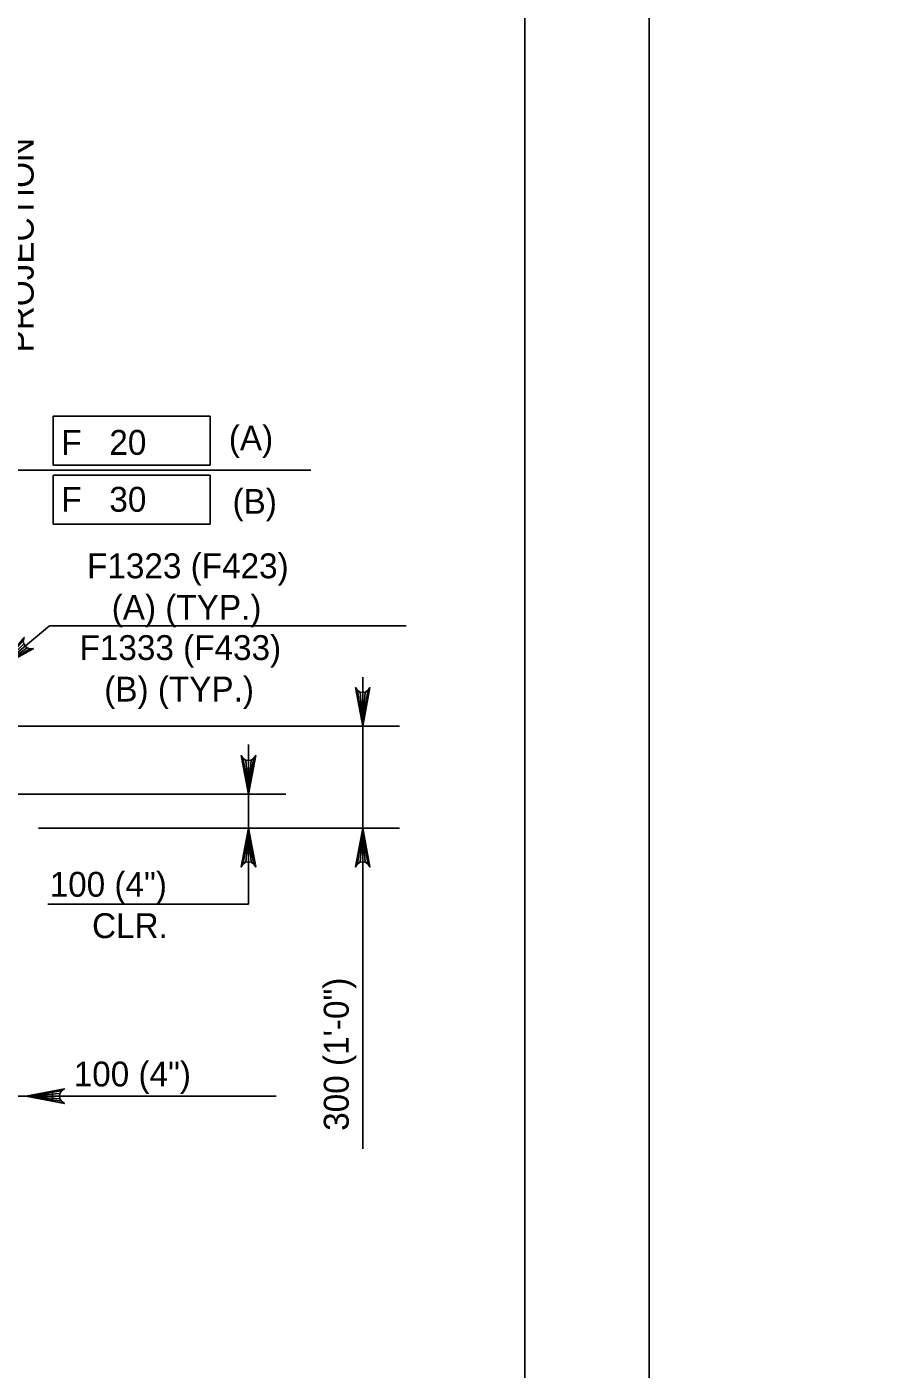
# Model space of a CAD drawing. Extents: x 638340 to 640241, y 295465 to 298435.
# Drawn here: x 639201.4 to 639303.6, y 296333.9 to 296495.7 of the extents above; entities that cross this region are included whole.
import ezdxf

# ---------------------------------------------------------------- set-up
doc = ezdxf.new("R2010")
doc.units = 0
for name, color, linetype in [('2', 7, 'Continuous'), ('3', 7, 'Continuous'), ('4', 7, 'Continuous'), ('PLT-BNDY', 7, 'Continuous')]:
    doc.layers.add(name, color=color, linetype=linetype)

msp = doc.modelspace()

# ---------------------------------------------------------------- linework, layer by layer
at = {"layer": '2'}
msp.add_line((639261.46, 296638.46), (639261.46, 296074.46), dxfattribs=at)
at = {"layer": '3'}
for p, q in [((639241.91, 296414.33), (639241.91, 296417.29)), ((639190.27, 296411.38), (639246.34, 296411.38)), ((639241.91, 296411.38), (639241.91, 296399.08)), ((639228.13, 296406.18), (639228.13, 296409.18)), ((639199.63, 296403.18), (639232.63, 296403.18)), ((639228.13, 296403.18), (639228.13, 296399.08)), ((639202.82, 296399.08), (639246.34, 296399.08)), ((639202.85, 296399.08), (639232.63, 296399.08)), ((639228.13, 296396.08), (639228.13, 296389.91)), ((639241.91, 296396.13), (639241.91, 296360.41)), ((639228.13, 296389.91), (639203.96, 296389.91))]:
    msp.add_line(p, q, dxfattribs=at)
for points in [[(639241.91, 296411.38), (639241.03, 296416.04), (639241.28, 296415.68), (639241.6, 296415.5), (639241.91, 296415.44), (639242.22, 296415.5), (639242.53, 296415.68), (639242.78, 296416.04), (639241.91, 296411.38), (639242.53, 296415.68), (639242.22, 296415.5), (639241.91, 296411.38), (639241.91, 296415.44), (639241.6, 296415.5), (639241.91, 296411.38), (639241.28, 296415.68)], [(639228.13, 296403.18), (639227.26, 296407.84), (639227.51, 296407.48), (639227.82, 296407.3), (639228.13, 296407.24), (639228.45, 296407.3), (639228.76, 296407.48), (639229.01, 296407.84), (639228.13, 296403.18), (639228.76, 296407.48), (639228.45, 296407.3), (639228.13, 296403.18), (639228.13, 296407.24), (639227.82, 296407.3), (639228.13, 296403.18), (639227.51, 296407.48)], [(639228.13, 296399.08), (639229.01, 296394.42), (639228.76, 296394.78), (639228.45, 296394.97), (639228.13, 296395.02), (639227.82, 296394.97), (639227.51, 296394.78), (639227.26, 296394.42), (639228.13, 296399.08), (639227.51, 296394.78), (639227.82, 296394.97), (639228.13, 296399.08), (639228.13, 296395.02), (639228.45, 296394.97), (639228.13, 296399.08), (639228.76, 296394.78)], [(639241.91, 296399.08), (639242.78, 296394.42), (639242.53, 296394.78), (639242.22, 296394.97), (639241.91, 296395.02), (639241.6, 296394.97), (639241.28, 296394.78), (639241.03, 296394.42), (639241.91, 296399.08), (639241.28, 296394.78), (639241.6, 296394.97), (639241.91, 296399.08), (639241.91, 296395.02), (639242.22, 296394.97), (639241.91, 296399.08), (639242.53, 296394.78)]]:
    msp.add_lwpolyline(points, dxfattribs=at)
for points in [[(639241.42, 296414.33), (639242.4, 296414.33), (639241.91, 296411.38)], [(639227.63, 296406.18), (639228.63, 296406.18), (639228.13, 296403.18)], [(639227.63, 296396.08), (639228.63, 296396.08), (639228.13, 296399.08)], [(639241.42, 296396.13), (639242.4, 296396.13), (639241.91, 296399.08)]]:
    msp.add_lwpolyline(points, close=True, dxfattribs=at)
at = {"layer": '4'}
for p, q in [((639204.6, 296448.77), (639223.54, 296448.77)), ((639204.6, 296442.86), (639204.6, 296448.77)), ((639223.54, 296448.77), (639223.54, 296442.86)), ((639199.78, 296442.24), (639235.65, 296442.24)), ((639223.54, 296442.86), (639204.6, 296442.86)), ((639204.6, 296441.65), (639223.54, 296441.65)), ((639204.6, 296435.75), (639204.6, 296441.65)), ((639223.54, 296441.65), (639223.54, 296435.75)), ((639223.54, 296435.75), (639204.6, 296435.75)), ((639204.15, 296423.47), (639198.07, 296418.45)), ((639204.15, 296423.47), (639247.14, 296423.47)), ((639197.21, 296366.78), (639231.47, 296366.78))]:
    msp.add_line(p, q, dxfattribs=at)
for points in [[(639198.07, 296418.45), (639201.11, 296422.09), (639200.99, 296421.67), (639201.04, 296421.31), (639201.2, 296421.04), (639201.44, 296420.83), (639201.78, 296420.71), (639202.22, 296420.74), (639198.07, 296418.45), (639201.78, 296420.71), (639201.44, 296420.83), (639198.07, 296418.45), (639201.2, 296421.04), (639201.04, 296421.31), (639198.07, 296418.45), (639200.99, 296421.67)], [(639201.28, 296366.78), (639205.94, 296367.65), (639205.58, 296367.41), (639205.4, 296367.09), (639205.34, 296366.78), (639205.4, 296366.47), (639205.58, 296366.16), (639205.94, 296365.91), (639201.28, 296366.78), (639205.58, 296366.16), (639205.4, 296366.47), (639201.28, 296366.78), (639205.34, 296366.78), (639205.4, 296367.09), (639201.28, 296366.78), (639205.58, 296367.41)]]:
    msp.add_lwpolyline(points, dxfattribs=at)
msp.add_lwpolyline([(639204.51, 296367.28), (639204.51, 296366.29), (639201.56, 296366.78)], close=True, dxfattribs=at)
at = {"layer": 'PLT-BNDY'}
for points in [[(638435.46, 296653.46), (639276.46, 296653.46), (639276.46, 296059.46), (638435.46, 296059.46)], [(639276.46, 296653.46), (640117.46, 296653.46), (640117.46, 296059.46), (639276.46, 296059.46)]]:
    msp.add_lwpolyline(points, close=True, dxfattribs=at)

# ---------------------------------------------------------------- texts
at = {"layer": '3'}
for s, p in [('100 (4")', (639204.17, 296390.82)), ('CLR.', (639209.28, 296385.83)), ('100 (4")', (639207.07, 296367.95))]:
    msp.add_text(s, height=3, dxfattribs=at).set_placement(p)
msp.add_text('300 (1\'-0")', height=3.0001, rotation=90, dxfattribs=at).set_placement((639240.22, 296362.6))
at = {"layer": '4'}
msp.add_text('PROJECTION', height=3, rotation=90, dxfattribs=at).set_placement((639202.24, 296456.44))
for s, height, p in [('F   20', 3, (639205.57, 296444.09)), ('(A)', 3, (639225.77, 296444.62)), ('F   30', 3, (639205.57, 296437.23)), ('(B)', 3, (639226.22, 296436.98)), ('F1323 (F423)', 3.0001, (639208.68, 296429.21)), ('(A) (TYP.)', 3, (639211.65, 296424.21)), ('F1333 (F433)', 3.0001, (639207.77, 296419.35)), ('(B) (TYP.)', 3, (639210.75, 296414.35))]:
    msp.add_text(s, height=height, dxfattribs=at).set_placement(p)

doc.saveas('drawing.dxf')
